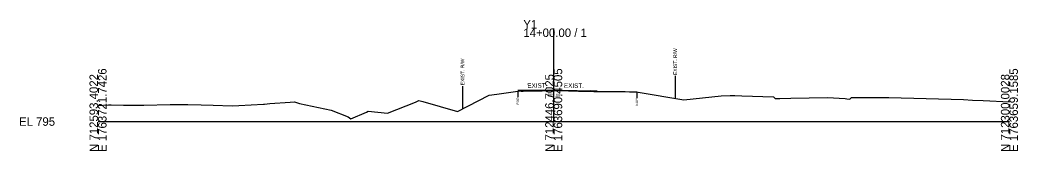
# Model space of a CAD drawing. Extents: x -26 to 1303, y -10 to 9524.
# Drawn here: x -25.7 to 302.8, y 3990.3 to 4033.4 of the extents above; entities that cross this region are included whole.
import ezdxf

# ---------------------------------------------------------------- set-up
doc = ezdxf.new("R2010")
doc.units = 0
for name, color, linetype in [('Default', 7, 'Continuous'), ('Exist Cross Section Cell', 7, 'Continuous'), ('Exist XS Center Line Elevation Label', 7, 'Continuous'), ('Exist XS Ground Line', 7, 'Continuous'), ('Old_Level_10', 7, 'Continuous'), ('Prop CMT Pvmt Surface Overlay', 7, 'Continuous'), ('Prop XS Earthwork Shape', 7, 'Continuous'), ('Prop XS SE Text', 7, 'Continuous')]:
    doc.layers.add(name, color=color, linetype=linetype)

msp = doc.modelspace()

# ---------------------------------------------------------------- linework, layer by layer
at = {"layer": 'Exist Cross Section Cell'}
for p, q in [((150, 4000), (150, 4030.58)), ((0, 4000), (150, 4000)), ((150, 4000), (300, 4000))]:
    msp.add_line(p, q, dxfattribs=at)
at = {"layer": 'Exist XS Ground Line'}
msp.add_lwpolyline([(0, 4005.31), (3.48, 4005.49), (4.34, 4005.49), (8.35, 4005.41), (15.11, 4005.34), (23.76, 4005.62), (29.52, 4005.64), (33.99, 4005.53), (37.95, 4005.39), (44.21, 4005.19), (46.38, 4005.25), (54.44, 4005.74), (54.81, 4005.75), (56.55, 4005.9), (63.24, 4006.39), (64.66, 4006.44), (66.28, 4005.9), (76.79, 4003.71), (82.32, 4001.5), (83.26, 4000.88), (88.42, 4003.13), (88.9, 4003.42), (95.34, 4002.72), (104.49, 4006.41), (105.57, 4006.94), (106.95, 4006.55), (118.31, 4003.33), (121.69, 4005.1), (128.71, 4008.72), (131.26, 4009.04), (138.23, 4010.03), (138.8, 4010.04), (139.31, 4010.02), (139.9, 4010.03), (140.24, 4010.05), (141.28, 4010.07), (142.79, 4010.08), (143.39, 4010.09), (145.49, 4010.13), (146.17, 4010.14), (147.6, 4010.16), (147.91, 4010.16), (149.01, 4010.18), (149.76, 4010.19), (150.46, 4010.19), (151.63, 4010.17), (153.02, 4010.15), (154.88, 4010.12), (155.58, 4010.12), (158.15, 4010.02), (159.75, 4010.02), (160.24, 4010), (160.69, 4009.98), (161.38, 4009.96), (163.24, 4009.9), (164.62, 4009.89), (165.8, 4009.88), (167.87, 4009.89), (168.36, 4009.89), (170.14, 4009.87), (171.12, 4009.86), (173.47, 4009.85), (174.99, 4009.79), (176.03, 4009.76), (177.33, 4009.73), (177.76, 4009.68), (192.85, 4007.1), (205.07, 4008.4), (208.06, 4008.59), (208.38, 4008.57), (208.86, 4008.58), (209.6, 4008.56), (211.97, 4008.49), (222.36, 4008.08), (222.87, 4007.57), (223.51, 4007.59), (224.39, 4007.61), (228.07, 4007.65), (240.12, 4007.9), (245.92, 4007.54), (246.47, 4007.49), (247.47, 4007.4), (247.99, 4007.88), (260.35, 4007.94), (284.86, 4007.2), (287.8, 4007.03), (291.32, 4006.93), (300, 4006.46)], dxfattribs=at)
at = {"layer": 'Old_Level_10'}
for p, q in [((190, 4014.99), (190, 4007.59)), ((120, 4011.62), (120, 4004.22)), ((138.23, 4010.03), (138.23, 4007.98)), ((177.33, 4009.73), (177.33, 4007.68))]:
    msp.add_line(p, q, dxfattribs=at)
at = {"layer": 'Prop CMT Pvmt Surface Overlay'}
for p, q in [((164.29, 4010.02), (162, 4010.08)), ((164.28, 4009.89), (162, 4009.95))]:
    msp.add_line(p, q, dxfattribs=at)
for points in [[(150, 4010.32), (138.23, 4010.15)], [(150, 4010.19), (138.23, 4010.03)], [(150, 4010.32), (162, 4010.08)], [(150, 4010.19), (162, 4009.95)]]:
    msp.add_lwpolyline(points, dxfattribs=at)
at = {"layer": 'Prop XS Earthwork Shape'}
for points in [[(138.23, 4010.03), (138.9, 4010.04), (138.8, 4010.04)], [(139.31, 4010.02), (139.9, 4010.03), (140.24, 4010.05), (141.22, 4010.07), (138.9, 4010.04)], [(141.22, 4010.07), (141.28, 4010.07), (141.4, 4010.07)], [(145.49, 4010.13), (146.17, 4010.14), (141.4, 4010.07), (142.79, 4010.08), (143.39, 4010.09)], [(147.6, 4010.16), (147.91, 4010.16), (148.06, 4010.17)], [(148.06, 4010.17), (149.01, 4010.18), (149.45, 4010.18)], [(149.45, 4010.18), (149.76, 4010.19), (150, 4010.19)], [(154.88, 4010.12), (155.58, 4010.12), (157.71, 4010.04), (150, 4010.19), (150.46, 4010.19), (151.63, 4010.17), (153.02, 4010.15)], [(158.15, 4010.02), (158.54, 4010.02), (157.71, 4010.04)], [(160.69, 4009.98), (161.02, 4009.97), (158.54, 4010.02), (159.75, 4010.02), (160.24, 4010)], [(161.38, 4009.96), (163.24, 4009.9), (164.28, 4009.89), (162, 4009.95), (161.02, 4009.97)]]:
    msp.add_lwpolyline(points, close=True, dxfattribs=at)

# ---------------------------------------------------------------- texts
at = {"layer": 'Default'}
msp.add_text('-', height=0.0001, dxfattribs=at).set_placement((0, 4000))
at = {"layer": 'Exist Cross Section Cell'}
for s, p in [('Y1', (140, 4030.58)), ('14+00.00 / 1', (140, 4027.78)), ('EL 795', (-26, 3998.6))]:
    msp.add_text(s, height=2.8, dxfattribs=at).set_placement(p)
for s, p in [('N 712593.4022', (0, 3990)), ('E 1763721.7426', (2.8, 3990)), ('N 712446.7025', (150, 3990)), ('E 1763690.4505', (152.8, 3990)), ('N 712300.0028', (300, 3990)), ('E 1763659.1585', (302.8, 3990))]:
    msp.add_text(s, height=2.8, rotation=90, dxfattribs=at).set_placement(p)
at = {"layer": 'Exist XS Center Line Elevation Label'}
msp.add_text('805.19', height=1, dxfattribs=at).set_placement((147.99, 4008.19))
at = {"layer": 'Old_Level_10'}
for s, height, p in [('EXIST. R/W', 1.181, (190.59, 4015.29)), ('EXIST. R/W', 1.181, (120.59, 4011.92)), ('EOP', 0.787, (138.62, 4005.58)), ('EOP', 0.787, (177.73, 4005.28))]:
    msp.add_text(s, height=height, rotation=90, dxfattribs=at).set_placement(p)
at = {"layer": 'Prop XS SE Text'}
for rotation, p in [(1.1458, (141.33, 4011.02)), (358.8542, (153.37, 4011.12))]:
    msp.add_text('EXIST.', height=1.5, rotation=rotation, dxfattribs=at).set_placement(p)

doc.saveas('drawing.dxf')
